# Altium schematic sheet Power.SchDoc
size A; DocumentNumber: 2; SheetNumber: 2; SheetTotal: 5
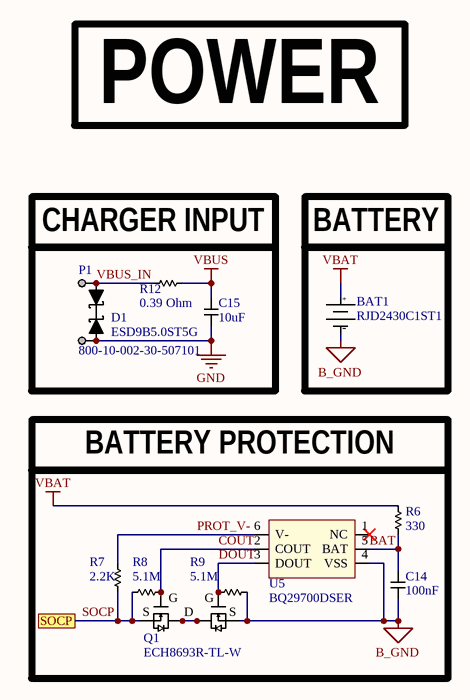
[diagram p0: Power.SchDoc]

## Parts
BAT1  RJD2430C1ST1  [RJD2430C1ST1]
C14  100nF  [CAP_0603_HIGH]
C15  10uF  [CAP_0603_HIGH]
D1  ESD9B5.0ST5G  [ESD9B5.0ST5G]
P1  800-10-002-30-507101  [800-10-002-30-507101]
Q1  ECH8693R-TL-W  [ECH8693R-TL-W]
R6  330  [RES_0603_HIGH]
R7  2.2K  [RES_0603_HIGH]
R8  5.1M  [RES_0603_HIGH]
R9  5.1M  [RES_0603_HIGH]
R12  0.39 Ohm  [RES_0805_HIGH]
U5  BQ29700DSER  [BQ29700DSER]

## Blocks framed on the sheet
CHARGER INPUT: C15 D1 P1 R12
BATTERY: BAT1
BATTERY PROTECTION: C14 Q1 R6-R9 U5

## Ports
SOCP

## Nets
B_GND: BAT1.2(-) C14.2 Q1.3(S2) R9.1 U5.4(VSS)
GND: C15.2 D1.1 P1.2
VBAT: BAT1.1(+) R6.1
VBUS: C15.1 R12.2
BAT: C14.1 R6.2 U5.5(BAT)
COUT: Q1.2(G1) R8.1 U5.2(COUT)
DOUT: Q1.4(G2) R9.2 U5.3(DOUT)
PROT_V-: R7.1 U5.6(V-)
SOCP: Q1.1(S1) R7.2 R8.2 ; port SOCP
VBUS_IN: D1.2 P1.1 R12.1
NetQ1_5: Q1.5(D) Q1.6(D) Q1.7(D) Q1.8(D)

Not connected (* = marked no-connect by the designer): U5 1(NC)*

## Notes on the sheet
- POWER

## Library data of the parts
BAT1 = RJD2430C1ST1: Coin, 24.5mm 3.7V Lithium-Ion Battery Rechargeable (Secondary) 110mAh
C14 C15 = Capacitor_0603: 0603 Capacitor
D1 = ESD9B5.0ST5G: TVS DIODE 5V SOD923
P1 = 800-10-002-30-507101: 2 Position Spring Mating Target Connector Surface Mount
Q1 = ECH8693R-TL-W: Mosfet Array 2 N-Channel (Dual) Common Drain 24V 14A 1.4W Surface Mount SOT-28FL/ECH8
R6-R9 = Resistor_0603: 0603 Resistor
R12 = Resistor_0805: 0805 Resistor
U5 = BQ29700DSER: Battery Battery Protection IC Lithium-Ion/Polymer 6-WSON (1.5x1.5)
